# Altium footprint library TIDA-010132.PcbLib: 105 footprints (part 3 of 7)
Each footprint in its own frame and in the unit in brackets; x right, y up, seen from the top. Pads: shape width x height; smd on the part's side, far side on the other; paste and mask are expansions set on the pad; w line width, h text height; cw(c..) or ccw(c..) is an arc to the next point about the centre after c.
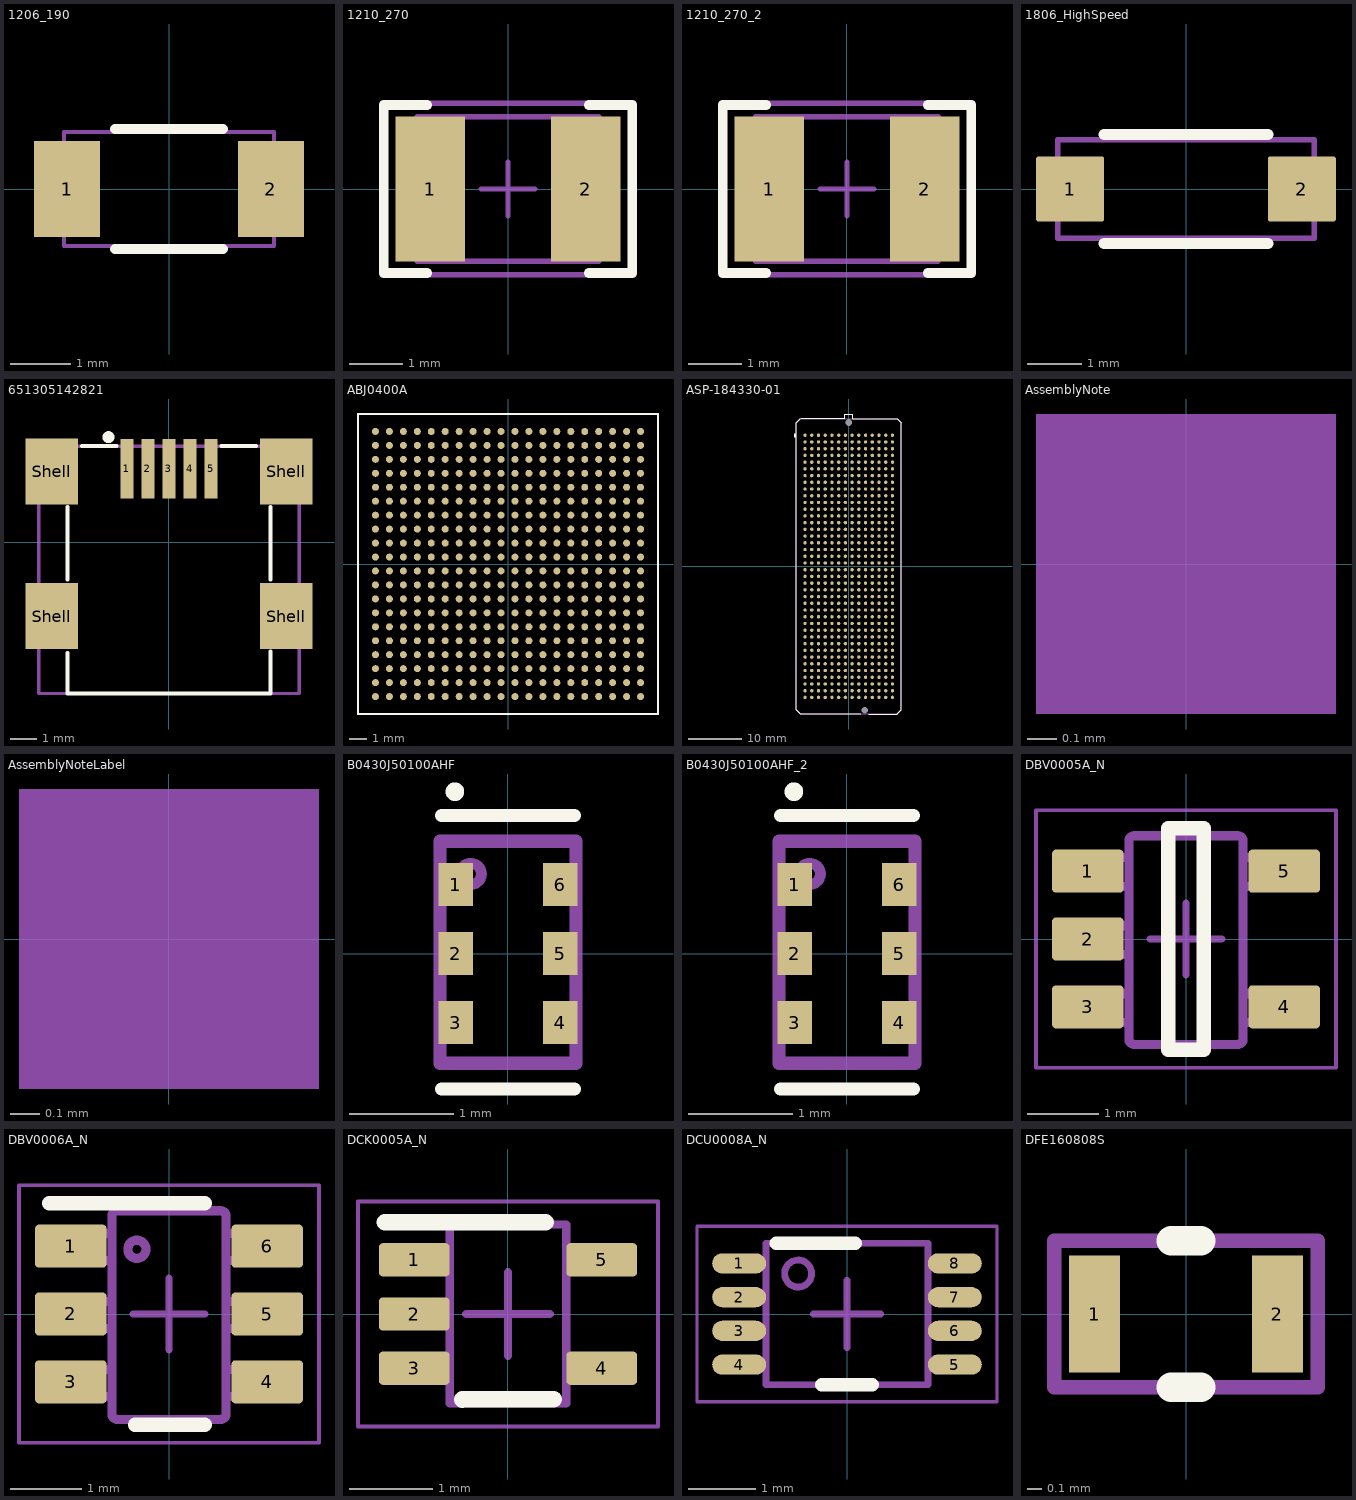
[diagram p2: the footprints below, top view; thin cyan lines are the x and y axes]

## 1206_190 [mm] "1206_190"
height 1.9
pads (2):
  rect 1.1x1.6 smd: 1(-1.7,0) 2(1.7,0)
Top Overlay:
  lines w0.17: -0.9,-1 0.9,-1 ; -0.9,1 0.9,1
Mechanical 5:
  lines w0.07: -1.75,-0.95 -1.75,0.95 1.75,0.95 1.75,-0.95 -1.75,-0.95
  text ".Designator" at -1.5,-0.4 h0.46
3D body: height 1.9, standoff 0, extent 1.301,-0.949 1.749,0.949
3D body: height 1.9, standoff 0, extent -1.299,-0.949 1.299,0.949
3D body: height 1.9, standoff 0, extent -1.749,-0.949 -1.301,0.949

## 1210_270 [mm] "1210"
height 2.7
pads (2):
  rect 1.3x2.7 smd: 1(-1.45,0) 2(1.45,0)
Top Overlay:
  lines w0.178: -1.511,-1.568 -2.316,-1.568 -2.316,1.568 -1.511,1.568 ; 1.511,-1.568 2.316,-1.568 2.316,1.568 1.511,1.568
Mechanical 5:
  lines w0.1: -1.7,-1.35 -1.7,1.35 1.7,1.35 1.7,-1.35 -1.7,-1.35
  text ".Designator" at -1.4,-0.375 h0.46
Mechanical 13:
  lines w0.1: -1.2,-1.35 -1.2,1.35 ; 1.2,-1.35 1.2,1.35 ; -1.7,-1.35 1.7,-1.35 1.7,1.35 -1.7,1.35 -1.7,-1.35
Mechanical 15:
  lines w0.1: -0.5,0 0.5,0 ; 0,-0.5 0,0.5 ; -2.35,-1.6 2.35,-1.6 2.35,1.6 -2.35,1.6 -2.35,-1.6
3D body: height 2.7, standoff 0, extent 1.201,-1.349 1.699,1.349
3D body: height 2.7, standoff 0, extent -1.199,-1.349 1.199,1.349
3D body: height 2.7, standoff 0, extent -1.699,-1.349 -1.201,1.349

## 1210_270_2 [mm]
pads (2):
  rect 1.3x2.7 smd: 1(-1.45,0) 2(1.45,0)
Top Overlay:
  lines w0.178: -1.511,-1.568 -2.316,-1.568 -2.316,1.568 -1.511,1.568 ; 1.511,-1.568 2.316,-1.568 2.316,1.568 1.511,1.568
Mechanical 5:
  lines w0.1: -1.7,-1.35 -1.7,1.35 1.7,1.35 1.7,-1.35 -1.7,-1.35
  text ".Designator" at -1.4,-0.375 h0.46
Mechanical 13:
  lines w0.1: -1.2,-1.35 -1.2,1.35 ; 1.2,-1.35 1.2,1.35 ; -1.7,-1.35 1.7,-1.35 1.7,1.35 -1.7,1.35 -1.7,-1.35
Mechanical 15:
  lines w0.1: -0.5,0 0.5,0 ; 0,-0.5 0,0.5 ; -2.35,-1.6 2.35,-1.6 2.35,1.6 -2.35,1.6 -2.35,-1.6
3D body: height 2.7, standoff 0, extent 1.201,-1.349 1.699,1.349
3D body: height 2.7, standoff 0, extent -1.199,-1.349 1.199,1.349
3D body: height 2.7, standoff 0, extent -1.699,-1.349 -1.201,1.349

## 1806_HighSpeed [mm] "Wurth recommended land pattern"
height 1.85
pads (2):
  rrect8% 1.25x1.2 smd: 1(-2.125,0) 2(2.125,0)
Top Overlay:
  lines w0.2: -1.5,-1 1.5,-1 ; -1.5,1 1.5,1
Mechanical 5:
  lines w0.1: -2.35,-0.9 -2.35,0.9 2.35,0.9 2.35,-0.9 -2.35,-0.9
  text ".Designator" at -1.7,-0.6 h0.46
3D body "1806.stp": height 1.61, standoff 0.01, extent -2.25,-0.8 2.25,0.8

## 651305142821 [mm] "5 pins"
height 4
pads (9):
  rect 0.5x2.25 smd: 1(-1.6,2.8) 2(-0.8,2.8) 3(0,2.8) 4(0.8,2.8) 5(1.6,2.8)
  rect 2x2.5 smd: Shell(-4.45,-2.8) Shell(-4.45,2.7) Shell(4.45,-2.8) Shell(4.45,2.7)
Top Overlay:
  circle w0.254: c-2.3,4 r0.1
  lines w0.152: -3.85,-4.2 -3.85,-5.74 3.85,-5.74 ; -3.85,-1.4 -3.85,1.35 ; -3.3,3.66 -1.99,3.66 ; 2,3.66 3.3,3.66 ; 3.85,-5.74 3.85,-4.15 ; 3.85,-1.4 3.85,1.35
Mechanical 5:
  lines w0.127: -4.95,-5.74 4.95,-5.74 4.95,3.66 -4.95,3.66 -4.95,-5.74
Mechanical 13:
  lines w0.127: -4.95,-5.74 -4.95,3.66 4.95,3.66 4.95,-5.74 -4.95,-5.74
3D body "651305142821.stp": height -0.4, standoff -4.5, extent -4.95,-5.74 4.95,3.66

## ABJ0400A [mm] "BGA, 400-Leads, Body 17.2x17.2mm, Pitch 0.8mm"
height 2.65
pads (400):
  round 0.4 smd: A1(-7.6,7.6) A2(-6.8,7.6) A3(-6,7.6) A4(-5.2,7.6) A5(-4.4,7.6) A6(-3.6,7.6) A7(-2.8,7.6) A8(-2,7.6) A9(-1.2,7.6) A10(-0.4,7.6) A11(0.4,7.6) A12(1.2,7.6) A13(2,7.6) A14(2.8,7.6) A15(3.6,7.6) A16(4.4,7.6) A17(5.2,7.6) A18(6,7.6) A19(6.8,7.6) A20(7.6,7.6) B1(-7.6,6.8) B2(-6.8,6.8) B3(-6,6.8) B4(-5.2,6.8) B5(-4.4,6.8) B6(-3.6,6.8) B7(-2.8,6.8) B8(-2,6.8) B9(-1.2,6.8) B10(-0.4,6.8) B11(0.4,6.8) B12(1.2,6.8) B13(2,6.8) B14(2.8,6.8) B15(3.6,6.8) B16(4.4,6.8) B17(5.2,6.8) B18(6,6.8) B19(6.8,6.8) B20(7.6,6.8) C1(-7.6,6) C2(-6.8,6) C3(-6,6) C4(-5.2,6) C5(-4.4,6) C6(-3.6,6) C7(-2.8,6) C8(-2,6) C9(-1.2,6) C10(-0.4,6) C11(0.4,6) C12(1.2,6) C13(2,6) C14(2.8,6) C15(3.6,6) C16(4.4,6) C17(5.2,6) C18(6,6) C19(6.8,6) C20(7.6,6) D1(-7.6,5.2) D2(-6.8,5.2) D3(-6,5.2) D4(-5.2,5.2) D5(-4.4,5.2) D6(-3.6,5.2) D7(-2.8,5.2) D8(-2,5.2) D9(-1.2,5.2) D10(-0.4,5.2) D11(0.4,5.2) D12(1.2,5.2) D13(2,5.2) D14(2.8,5.2) D15(3.6,5.2) D16(4.4,5.2) D17(5.2,5.2) D18(6,5.2) D19(6.8,5.2) D20(7.6,5.2) E1(-7.6,4.4) E2(-6.8,4.4) E3(-6,4.4) E4(-5.2,4.4) E5(-4.4,4.4) E6(-3.6,4.4) E7(-2.8,4.4) E8(-2,4.4) E9(-1.2,4.4) E10(-0.4,4.4) E11(0.4,4.4) E12(1.2,4.4) E13(2,4.4) E14(2.8,4.4) E15(3.6,4.4) E16(4.4,4.4) E17(5.2,4.4) E18(6,4.4) E19(6.8,4.4) E20(7.6,4.4) F1(-7.6,3.6) F2(-6.8,3.6) F3(-6,3.6) F4(-5.2,3.6) F5(-4.4,3.6) F6(-3.6,3.6) F7(-2.8,3.6) F8(-2,3.6) F9(-1.2,3.6) F10(-0.4,3.6) F11(0.4,3.6) F12(1.2,3.6) F13(2,3.6) F14(2.8,3.6) F15(3.6,3.6) F16(4.4,3.6) F17(5.2,3.6) F18(6,3.6) F19(6.8,3.6) F20(7.6,3.6) G1(-7.6,2.8) G2(-6.8,2.8) G3(-6,2.8) G4(-5.2,2.8) G5(-4.4,2.8) G6(-3.6,2.8) G7(-2.8,2.8) G8(-2,2.8) G9(-1.2,2.8) G10(-0.4,2.8) G11(0.4,2.8) G12(1.2,2.8) G13(2,2.8) G14(2.8,2.8) G15(3.6,2.8) G16(4.4,2.8) G17(5.2,2.8) G18(6,2.8) G19(6.8,2.8) G20(7.6,2.8) H1(-7.6,2) H2(-6.8,2) H3(-6,2) H4(-5.2,2) H5(-4.4,2) H6(-3.6,2) H7(-2.8,2) H8(-2,2) H9(-1.2,2) H10(-0.4,2) H11(0.4,2) H12(1.2,2) H13(2,2) H14(2.8,2) H15(3.6,2) H16(4.4,2) H17(5.2,2) H18(6,2) H19(6.8,2) H20(7.6,2) J1(-7.6,1.2) J2(-6.8,1.2) J3(-6,1.2) J4(-5.2,1.2) J5(-4.4,1.2) J6(-3.6,1.2) J7(-2.8,1.2) J8(-2,1.2) J9(-1.2,1.2) J10(-0.4,1.2) J11(0.4,1.2) J12(1.2,1.2) J13(2,1.2) J14(2.8,1.2) J15(3.6,1.2) J16(4.4,1.2) J17(5.2,1.2) J18(6,1.2) J19(6.8,1.2) J20(7.6,1.2) K1(-7.6,0.4) K2(-6.8,0.4) K3(-6,0.4) K4(-5.2,0.4) K5(-4.4,0.4) K6(-3.6,0.4) K7(-2.8,0.4) K8(-2,0.4) K9(-1.2,0.4) K10(-0.4,0.4) K11(0.4,0.4) K12(1.2,0.4) K13(2,0.4) K14(2.8,0.4) K15(3.6,0.4) K16(4.4,0.4) K17(5.2,0.4) K18(6,0.4) K19(6.8,0.4) K20(7.6,0.4) L1(-7.6,-0.4) L2(-6.8,-0.4) L3(-6,-0.4) L4(-5.2,-0.4) L5(-4.4,-0.4) L6(-3.6,-0.4) L7(-2.8,-0.4) L8(-2,-0.4) L9(-1.2,-0.4) L10(-0.4,-0.4) L11(0.4,-0.4) L12(1.2,-0.4) L13(2,-0.4) L14(2.8,-0.4) L15(3.6,-0.4) L16(4.4,-0.4) L17(5.2,-0.4) L18(6,-0.4) L19(6.8,-0.4) L20(7.6,-0.4) M1(-7.6,-1.2) M2(-6.8,-1.2) M3(-6,-1.2) M4(-5.2,-1.2) M5(-4.4,-1.2) M6(-3.6,-1.2) M7(-2.8,-1.2) M8(-2,-1.2) M9(-1.2,-1.2) M10(-0.4,-1.2) M11(0.4,-1.2) M12(1.2,-1.2) M13(2,-1.2) M14(2.8,-1.2) M15(3.6,-1.2) M16(4.4,-1.2) M17(5.2,-1.2) M18(6,-1.2) M19(6.8,-1.2) M20(7.6,-1.2) N1(-7.6,-2) N2(-6.8,-2) N3(-6,-2) N4(-5.2,-2) N5(-4.4,-2) N6(-3.6,-2) N7(-2.8,-2) N8(-2,-2) N9(-1.2,-2) N10(-0.4,-2) N11(0.4,-2) N12(1.2,-2) N13(2,-2) N14(2.8,-2) N15(3.6,-2) N16(4.4,-2) N17(5.2,-2) N18(6,-2) N19(6.8,-2) N20(7.6,-2) P1(-7.6,-2.8) P2(-6.8,-2.8) P3(-6,-2.8) P4(-5.2,-2.8) P5(-4.4,-2.8) P6(-3.6,-2.8) P7(-2.8,-2.8) P8(-2,-2.8) P9(-1.2,-2.8) P10(-0.4,-2.8) P11(0.4,-2.8) P12(1.2,-2.8) P13(2,-2.8) P14(2.8,-2.8) P15(3.6,-2.8) P16(4.4,-2.8) P17(5.2,-2.8) P18(6,-2.8) P19(6.8,-2.8) P20(7.6,-2.8) R1(-7.6,-3.6) R2(-6.8,-3.6) R3(-6,-3.6) R4(-5.2,-3.6) R5(-4.4,-3.6) R6(-3.6,-3.6) R7(-2.8,-3.6) R8(-2,-3.6) R9(-1.2,-3.6) R10(-0.4,-3.6) R11(0.4,-3.6) R12(1.2,-3.6) R13(2,-3.6) R14(2.8,-3.6) R15(3.6,-3.6) R16(4.4,-3.6) R17(5.2,-3.6) R18(6,-3.6) R19(6.8,-3.6) R20(7.6,-3.6) T1(-7.6,-4.4) T2(-6.8,-4.4) T3(-6,-4.4) T4(-5.2,-4.4) T5(-4.4,-4.4) T6(-3.6,-4.4) T7(-2.8,-4.4) T8(-2,-4.4) T9(-1.2,-4.4) T10(-0.4,-4.4) T11(0.4,-4.4) T12(1.2,-4.4) T13(2,-4.4) T14(2.8,-4.4) T15(3.6,-4.4) T16(4.4,-4.4) T17(5.2,-4.4) T18(6,-4.4) T19(6.8,-4.4) T20(7.6,-4.4) U1(-7.6,-5.2) U2(-6.8,-5.2) U3(-6,-5.2) U4(-5.2,-5.2) U5(-4.4,-5.2) U6(-3.6,-5.2) U7(-2.8,-5.2) U8(-2,-5.2) U9(-1.2,-5.2) U10(-0.4,-5.2) U11(0.4,-5.2) U12(1.2,-5.2) U13(2,-5.2) U14(2.8,-5.2) U15(3.6,-5.2) U16(4.4,-5.2) U17(5.2,-5.2) U18(6,-5.2) U19(6.8,-5.2) U20(7.6,-5.2) V1(-7.6,-6) V2(-6.8,-6) V3(-6,-6) V4(-5.2,-6) V5(-4.4,-6) V6(-3.6,-6) V7(-2.8,-6) V8(-2,-6) V9(-1.2,-6) V10(-0.4,-6) V11(0.4,-6) V12(1.2,-6) V13(2,-6) V14(2.8,-6) V15(3.6,-6) V16(4.4,-6) V17(5.2,-6) V18(6,-6) V19(6.8,-6) V20(7.6,-6) W1(-7.6,-6.8) W2(-6.8,-6.8) W3(-6,-6.8) W4(-5.2,-6.8) W5(-4.4,-6.8) W6(-3.6,-6.8) W7(-2.8,-6.8) W8(-2,-6.8) W9(-1.2,-6.8) W10(-0.4,-6.8) W11(0.4,-6.8) W12(1.2,-6.8) W13(2,-6.8) W14(2.8,-6.8) W15(3.6,-6.8) W16(4.4,-6.8) W17(5.2,-6.8) W18(6,-6.8) W19(6.8,-6.8) W20(7.6,-6.8) Y1(-7.6,-7.6) Y2(-6.8,-7.6) Y3(-6,-7.6) Y4(-5.2,-7.6) Y5(-4.4,-7.6) Y6(-3.6,-7.6) Y7(-2.8,-7.6) Y8(-2,-7.6) Y9(-1.2,-7.6) Y10(-0.4,-7.6) Y11(0.4,-7.6) Y12(1.2,-7.6) Y13(2,-7.6) Y14(2.8,-7.6) Y15(3.6,-7.6) Y16(4.4,-7.6) Y17(5.2,-7.6) Y18(6,-7.6) Y19(6.8,-7.6) Y20(7.6,-7.6)
Top Overlay:
  lines w0.1: -8.6,-8.6 8.6,-8.6 8.6,8.6 -8.6,8.6 -8.6,-8.6
Mechanical 5:
  lines w0.1: -8.6,-8.6 -8.6,8.6 8.6,8.6 8.6,-8.6 -8.6,-8.6
  text ".Designator" at -1.7,-0.5 h0.46
3D body: height 2.65, standoff 0.3, extent -8.6,-8.6 8.6,8.6

## ASP-184330-01 [mil] "Terminal Array, 1.27mm, 40x14, SMT"
height 285
pads (1122):
  round 25 smd paste-25.2: A1(-225,975) A2(-225,925) A3(-225,875) A4(-225,825) A5(-225,775) A6(-225,725) A7(-225,675) A8(-225,625) A9(-225,575) A10(-225,525) A11(-225,475) A12(-225,425) A13(-225,375) A14(-225,325) A15(-225,275) A16(-225,225) A17(-225,175) A18(-225,125) A19(-225,75) A20(-225,25) A21(-225,-25) A22(-225,-75) A23(-225,-125) A24(-225,-175) A25(-225,-225) A26(-225,-275) A27(-225,-325) A28(-225,-375) A29(-225,-425) A30(-225,-475) A31(-225,-525) A32(-225,-575) A33(-225,-625) A34(-225,-675) A35(-225,-725) A36(-225,-775) A37(-225,-825) A38(-225,-875) A39(-225,-925) A40(-225,-975) B1(-175,975) B2(-175,925) B3(-175,875) B4(-175,825) B5(-175,775) B6(-175,725) B7(-175,675) B8(-175,625) B9(-175,575) B10(-175,525) B11(-175,475) B12(-175,425) B13(-175,375) B14(-175,325) B15(-175,275) B16(-175,225) B17(-175,175) B18(-175,125) B19(-175,75) B20(-175,25) B21(-175,-25) B22(-175,-75) B23(-175,-125) B24(-175,-175) B25(-175,-225) B26(-175,-275) B27(-175,-325) B28(-175,-375) B29(-175,-425) B30(-175,-475) B31(-175,-525) B32(-175,-575) B33(-175,-625) B34(-175,-675) B35(-175,-725) B36(-175,-775) B37(-175,-825) B38(-175,-875) B39(-175,-925) B40(-175,-975) C1(-125,975) C2(-125,925) C3(-125,875) C4(-125,825) C5(-125,775) C6(-125,725) C7(-125,675) C8(-125,625) C9(-125,575) C10(-125,525) C11(-125,475) C12(-125,425) C13(-125,375) C14(-125,325) C15(-125,275) C16(-125,225) C17(-125,175) C18(-125,125) C19(-125,75) C20(-125,25) C21(-125,-25) C22(-125,-75) C23(-125,-125) C24(-125,-175) C25(-125,-225) C26(-125,-275) C27(-125,-325) C28(-125,-375) C29(-125,-425) C30(-125,-475) C31(-125,-525) C32(-125,-575) C33(-125,-625) C34(-125,-675) C35(-125,-725) C36(-125,-775) C37(-125,-825) C38(-125,-875) C39(-125,-925) C40(-125,-975) D1(-75,975) D2(-75,925) D3(-75,875) D4(-75,825) D5(-75,775) D6(-75,725) D7(-75,675) D8(-75,625) D9(-75,575) D10(-75,525) D11(-75,475) D12(-75,425) D13(-75,375) D14(-75,325) D15(-75,275) D16(-75,225) D17(-75,175) D18(-75,125) D19(-75,75) D20(-75,25) D21(-75,-25) D22(-75,-75) D23(-75,-125) D24(-75,-175) D25(-75,-225) D26(-75,-275) D27(-75,-325) D28(-75,-375) D29(-75,-425) D30(-75,-475) D31(-75,-525) D32(-75,-575) D33(-75,-625) D34(-75,-675) D35(-75,-725) D36(-75,-775) D37(-75,-825) D38(-75,-875) D39(-75,-925) D40(-75,-975) E1(-25,975) E2(-25,925) E3(-25,875) E4(-25,825) E5(-25,775) E6(-25,725) E7(-25,675) E8(-25,625) E9(-25,575) E10(-25,525) E11(-25,475) E12(-25,425) E13(-25,375) E14(-25,325) E15(-25,275) E16(-25,225) E17(-25,175) E18(-25,125) E19(-25,75) E20(-25,25) E21(-25,-25) E22(-25,-75) E23(-25,-125) E24(-25,-175) E25(-25,-225) E26(-25,-275) E27(-25,-325) E28(-25,-375) E29(-25,-425) E30(-25,-475) E31(-25,-525) E32(-25,-575) E33(-25,-625) E34(-25,-675) E35(-25,-725) E36(-25,-775) E37(-25,-825) E38(-25,-875) E39(-25,-925) E40(-25,-975) F1(25,975) F2(25,925) F3(25,875) F4(25,825) F5(25,775) F6(25,725) F7(25,675) F8(25,625) F9(25,575) F10(25,525) F11(25,475) F12(25,425) F13(25,375) F14(25,325) F15(25,275) F16(25,225) F17(25,175) F18(25,125) F19(25,75) F20(25,25) F21(25,-25) F22(25,-75) F23(25,-125) F24(25,-175) F25(25,-225) F26(25,-275) F27(25,-325) F28(25,-375) F29(25,-425) F30(25,-475) F31(25,-525) F32(25,-575) F33(25,-625) F34(25,-675) F35(25,-725) F36(25,-775) F37(25,-825) F38(25,-875) F39(25,-925) F40(25,-975) G1(75,975) G2(75,925) G3(75,875) G4(75,825) G5(75,775) G6(75,725) G7(75,675) G8(75,625) G9(75,575) G10(75,525) G11(75,475) G12(75,425) G13(75,375) G14(75,325) G15(75,275) G16(75,225) G17(75,175) G18(75,125) G19(75,75) G20(75,25) G21(75,-25) G22(75,-75) G23(75,-125) G24(75,-175) G25(75,-225) G26(75,-275) G27(75,-325) G28(75,-375) G29(75,-425) G30(75,-475) G31(75,-525) G32(75,-575) G33(75,-625) G34(75,-675) G35(75,-725) G36(75,-775) G37(75,-825) G38(75,-875) G39(75,-925) G40(75,-975) H1(125,975) H2(125,925) H3(125,875) H4(125,825) H5(125,775) H6(125,725) H7(125,675) H8(125,625) H9(125,575) H10(125,525) H11(125,475) H12(125,425) H13(125,375) H14(125,325) H15(125,275) H16(125,225) H17(125,175) H18(125,125) H19(125,75) H20(125,25) H21(125,-25) H22(125,-75) H23(125,-125) H24(125,-175) H25(125,-225) H26(125,-275) H27(125,-325) H28(125,-375) H29(125,-425) H30(125,-475) H31(125,-525) H32(125,-575) H33(125,-625) H34(125,-675) H35(125,-725) H36(125,-775) H37(125,-825) H38(125,-875) H39(125,-925) H40(125,-975) J1(175,975) J2(175,925) J3(175,875) J4(175,825) J5(175,775) J6(175,725) J7(175,675) J8(175,625) J9(175,575) J10(175,525) J11(175,475) J12(175,425) J13(175,375) J14(175,325) J15(175,275) J16(175,225) J17(175,175) J18(175,125) J19(175,75) J20(175,25) J21(175,-25) J22(175,-75) J23(175,-125) J24(175,-175) J25(175,-225) J26(175,-275) J27(175,-325) J28(175,-375) J29(175,-425) J30(175,-475) J31(175,-525) J32(175,-575) J33(175,-625) J34(175,-675) J35(175,-725) J36(175,-775) J37(175,-825) J38(175,-875) J39(175,-925) J40(175,-975) K1(225,975) K2(225,925) K3(225,875) K4(225,825) K5(225,775) K6(225,725) K7(225,675) K8(225,625) K9(225,575) K10(225,525) K11(225,475) K12(225,425) K13(225,375) K14(225,325) K15(225,275) K16(225,225) K17(225,175) K18(225,125) K19(225,75) K20(225,25) K21(225,-25) K22(225,-75) K23(225,-125) K24(225,-175) K25(225,-225) K26(225,-275) K27(225,-325) K28(225,-375) K29(225,-425) K30(225,-475) K31(225,-525) K32(225,-575) K33(225,-625) K34(225,-675) K35(225,-725) K36(225,-775) K37(225,-825) K38(225,-875) K39(225,-925) K40(225,-975) L1(275,975) L2(275,925) L3(275,875) L4(275,825) L5(275,775) L6(275,725) L7(275,675) L8(275,625) L9(275,575) L10(275,525) L11(275,475) L12(275,425) L13(275,375) L14(275,325) L15(275,275) L16(275,225) L17(275,175) L18(275,125) L19(275,75) L20(275,25) L21(275,-25) L22(275,-75) L23(275,-125) L24(275,-175) L25(275,-225) L26(275,-275) L27(275,-325) L28(275,-375) L29(275,-425) L30(275,-475) L31(275,-525) L32(275,-575) L33(275,-625) L34(275,-675) L35(275,-725) L36(275,-775) L37(275,-825) L38(275,-875) L39(275,-925) L40(275,-975) M1(325,975) M2(325,925) M3(325,875) M4(325,825) M5(325,775) M6(325,725) M7(325,675) M8(325,625) M9(325,575) M10(325,525) M11(325,475) M12(325,425) M13(325,375) M14(325,325) M15(325,275) M16(325,225) M17(325,175) M18(325,125) M19(325,75) M20(325,25) M21(325,-25) M22(325,-75) M23(325,-125) M24(325,-175) M25(325,-225) M26(325,-275) M27(325,-325) M28(325,-375) M29(325,-425) M30(325,-475) M31(325,-525) M32(325,-575) M33(325,-625) M34(325,-675) M35(325,-725) M36(325,-775) M37(325,-825) M38(325,-875) M39(325,-925) M40(325,-975) Y1(-325,975) Y2(-325,925) Y3(-325,875) Y4(-325,825) Y5(-325,775) Y6(-325,725) Y7(-325,675) Y8(-325,625) Y9(-325,575) Y10(-325,525) Y11(-325,475) Y12(-325,425) Y13(-325,375) Y14(-325,325) Y15(-325,275) Y16(-325,225) Y17(-325,175) Y18(-325,125) Y19(-325,75) Y20(-325,25) Y21(-325,-25) Y22(-325,-75) Y23(-325,-125) Y24(-325,-175) Y25(-325,-225) Y26(-325,-275) Y27(-325,-325) Y28(-325,-375) Y29(-325,-425) Y30(-325,-475) Y31(-325,-525) Y32(-325,-575) Y33(-325,-625) Y34(-325,-675) Y35(-325,-725) Y36(-325,-775) Y37(-325,-825) Y38(-325,-875) Y39(-325,-925) Y40(-325,-975) Z1(-275,975) Z2(-275,925) Z3(-275,875) Z4(-275,825) Z5(-275,775) Z6(-275,725) Z7(-275,675) Z8(-275,625) Z9(-275,575) Z10(-275,525) Z11(-275,475) Z12(-275,425) Z13(-275,375) Z14(-275,325) Z15(-275,275) Z16(-275,225) Z17(-275,175) Z18(-275,125) Z19(-275,75) Z20(-275,25) Z21(-275,-25) Z22(-275,-75) Z23(-275,-125) Z24(-275,-175) Z25(-275,-225) Z26(-275,-275) Z27(-275,-325) Z28(-275,-375) Z29(-275,-425) Z30(-275,-475) Z31(-275,-525) Z32(-275,-575) Z33(-275,-625) Z34(-275,-675) Z35(-275,-725) Z36(-275,-775) Z37(-275,-825) Z38(-275,-875) Z39(-275,-925) Z40(-275,-975)
  round 35 on Top Paste: ""(-325,-975) ""(-325,-925) ""(-325,-875) ""(-325,-825) ""(-325,-775) ""(-325,-725) ""(-325,-675) ""(-325,-625) ""(-325,-575) ""(-325,-525) ""(-325,-475) ""(-325,-425) ""(-325,-375) ""(-325,-325) ""(-325,-275) ""(-325,-225) ""(-325,-175) ""(-325,-125) ""(-325,-75) ""(-325,-25) ""(-325,25) ""(-325,75) ""(-325,125) ""(-325,175) ""(-325,225) ""(-325,275) ""(-325,325) ""(-325,375) ""(-325,425) ""(-325,475) ""(-325,525) ""(-325,575) ""(-325,625) ""(-325,675) ""(-325,725) ""(-325,775) ""(-325,825) ""(-325,875) ""(-325,925) ""(-325,975) ""(-275,-975) ""(-275,-925) ""(-275,-875) ""(-275,-825) ""(-275,-775) ""(-275,-725) ""(-275,-675) ""(-275,-625) ""(-275,-575) ""(-275,-525) ""(-275,-475) ""(-275,-425) ""(-275,-375) ""(-275,-325) ""(-275,-275) ""(-275,-225) ""(-275,-175) ""(-275,-125) ""(-275,-75) ""(-275,-25) ""(-275,25) ""(-275,75) ""(-275,125) ""(-275,175) ""(-275,225) ""(-275,275) ""(-275,325) ""(-275,375) ""(-275,425) ""(-275,475) ""(-275,525) ""(-275,575) ""(-275,625) ""(-275,675) ""(-275,725) ""(-275,775) ""(-275,825) ""(-275,875) ""(-275,925) ""(-275,975) ""(-225,-975) ""(-225,-925) ""(-225,-875) ""(-225,-825) ""(-225,-775) ""(-225,-725) ""(-225,-675) ""(-225,-625) ""(-225,-575) ""(-225,-525) ""(-225,-475) ""(-225,-425) ""(-225,-375) ""(-225,-325) ""(-225,-275) ""(-225,-225) ""(-225,-175) ""(-225,-125) ""(-225,-75) ""(-225,-25) ""(-225,25) ""(-225,75) ""(-225,125) ""(-225,175) ""(-225,225) ""(-225,275) ""(-225,325) ""(-225,375) ""(-225,425) ""(-225,475) ""(-225,525) ""(-225,575) ""(-225,625) ""(-225,675) ""(-225,725) ""(-225,775) ""(-225,825) ""(-225,875) ""(-225,925) ""(-225,975) ""(-175,-975) ""(-175,-925) ""(-175,-875) ""(-175,-825) ""(-175,-775) ""(-175,-725) ""(-175,-675) ""(-175,-625) ""(-175,-575) ""(-175,-525) ""(-175,-475) ""(-175,-425) ""(-175,-375) ""(-175,-325) ""(-175,-275) ""(-175,-225) ""(-175,-175) ""(-175,-125) ""(-175,-75) ""(-175,-25) ""(-175,25) ""(-175,75) ""(-175,125) ""(-175,175) ""(-175,225) ""(-175,275) ""(-175,325) ""(-175,375) ""(-175,425) ""(-175,475) ""(-175,525) ""(-175,575) ""(-175,625) ""(-175,675) ""(-175,725) ""(-175,775) ""(-175,825) ""(-175,875) ""(-175,925) ""(-175,975) ""(-125,-975) ""(-125,-925) ""(-125,-875) ""(-125,-825) ""(-125,-775) ""(-125,-725) ""(-125,-675) ""(-125,-625) ""(-125,-575) ""(-125,-525) ""(-125,-475) ""(-125,-425) ""(-125,-375) ""(-125,-325) ""(-125,-275) ""(-125,-225) ""(-125,-175) ""(-125,-125) ""(-125,-75) ""(-125,-25) ""(-125,25) ""(-125,75) ""(-125,125) ""(-125,175) ""(-125,225) ""(-125,275) ""(-125,325) ""(-125,375) ""(-125,425) ""(-125,475) ""(-125,525) ""(-125,575) ""(-125,625) ""(-125,675) ""(-125,725) ""(-125,775) ""(-125,825) ""(-125,875) ""(-125,925) ""(-125,975) ""(-75,-975) ""(-75,-925) ""(-75,-875) ""(-75,-825) ""(-75,-775) ""(-75,-725) ""(-75,-675) ""(-75,-625) ""(-75,-575) ""(-75,-525) ""(-75,-475) ""(-75,-425) ""(-75,-375) ""(-75,-325) ""(-75,-275) ""(-75,-225) ""(-75,-175) ""(-75,-125) ""(-75,-75) ""(-75,-25) ""(-75,25) ""(-75,75) ""(-75,125) ""(-75,175) ""(-75,225) ""(-75,275) ""(-75,325) ""(-75,375) ""(-75,425) ""(-75,475) ""(-75,525) ""(-75,575) ""(-75,625) ""(-75,675) ""(-75,725) ""(-75,775) ""(-75,825) ""(-75,875) ""(-75,925) ""(-75,975) ""(-25,-975) ""(-25,-925) ""(-25,-875) ""(-25,-825) ""(-25,-775) ""(-25,-725) ""(-25,-675) ""(-25,-625) ""(-25,-575) ""(-25,-525) ""(-25,-475) ""(-25,-425) ""(-25,-375) ""(-25,-325) ""(-25,-275) ""(-25,-225) ""(-25,-175) ""(-25,-125) ""(-25,-75) ""(-25,-25) ""(-25,25) ""(-25,75) ""(-25,125) ""(-25,175) ""(-25,225) ""(-25,275) ""(-25,325) ""(-25,375) ""(-25,425) ""(-25,475) ""(-25,525) ""(-25,575) ""(-25,625) ""(-25,675) ""(-25,725) ""(-25,775) ""(-25,825) ""(-25,875) ""(-25,925) ""(-25,975) ""(25,-975) ""(25,-925) ""(25,-875) ""(25,-825) ""(25,-775) ""(25,-725) ""(25,-675) ""(25,-625) ""(25,-575) ""(25,-525) ""(25,-475) ""(25,-425) ""(25,-375) ""(25,-325) ""(25,-275) ""(25,-225) ""(25,-175) ""(25,-125) ""(25,-75) ""(25,-25) ""(25,25) ""(25,75) ""(25,125) ""(25,175) ""(25,225) ""(25,275) ""(25,325) ""(25,375) ""(25,425) ""(25,475) ""(25,525) ""(25,575) ""(25,625) ""(25,675) ""(25,725) ""(25,775) ""(25,825) ""(25,875) ""(25,925) ""(25,975) ""(75,-975) ""(75,-925) ""(75,-875) ""(75,-825) ""(75,-775) ""(75,-725) ""(75,-675) ""(75,-625) ""(75,-575) ""(75,-525) ""(75,-475) ""(75,-425) ""(75,-375) ""(75,-325) ""(75,-275) ""(75,-225) ""(75,-175) ""(75,-125) ""(75,-75) ""(75,-25) ""(75,25) ""(75,75) ""(75,125) ""(75,175) ""(75,225) ""(75,275) ""(75,325) ""(75,375) ""(75,425) ""(75,475) ""(75,525) ""(75,575) ""(75,625) ""(75,675) ""(75,725) ""(75,775) ""(75,825) ""(75,875) ""(75,925) ""(75,975) ""(125,-975) ""(125,-925) ""(125,-875) ""(125,-825) ""(125,-775) ""(125,-725) ""(125,-675) ""(125,-625) ""(125,-575) ""(125,-525) ""(125,-475) ""(125,-425) ""(125,-375) ""(125,-325) ""(125,-275) ""(125,-225) ""(125,-175) ""(125,-125) ""(125,-75) ""(125,-25) ""(125,25) ""(125,75) ""(125,125) ""(125,175) ""(125,225) ""(125,275) ""(125,325) ""(125,375) ""(125,425) ""(125,475) ""(125,525) ""(125,575) ""(125,625) ""(125,675) ""(125,725) ""(125,775) ""(125,825) ""(125,875) ""(125,925) ""(125,975) ""(175,-975) ""(175,-925) ""(175,-875) ""(175,-825) ""(175,-775) ""(175,-725) ""(175,-675) ""(175,-625) ""(175,-575) ""(175,-525) ""(175,-475) ""(175,-425) ""(175,-375) ""(175,-325) ""(175,-275) ""(175,-225) ""(175,-175) ""(175,-125) ""(175,-75) ""(175,-25) ""(175,25) ""(175,75) ""(175,125) ""(175,175) ""(175,225) ""(175,275) ""(175,325) ""(175,375) ""(175,425) ""(175,475) ""(175,525) ""(175,575) ""(175,625) ""(175,675) ""(175,725) ""(175,775) ""(175,825) ""(175,875) ""(175,925) ""(175,975) ""(225,-975) ""(225,-925) ""(225,-875) ""(225,-825) ""(225,-775) ""(225,-725) ""(225,-675) ""(225,-625) ""(225,-575) ""(225,-525) ""(225,-475) ""(225,-425) ""(225,-375) ""(225,-325) ""(225,-275) ""(225,-225) ""(225,-175) ""(225,-125) ""(225,-75) ""(225,-25) ""(225,25) ""(225,75) ""(225,125) ""(225,175) ""(225,225) ""(225,275) ""(225,325) ""(225,375) ""(225,425) ""(225,475) ""(225,525) ""(225,575) ""(225,625) ""(225,675) ""(225,725) ""(225,775) ""(225,825) ""(225,875) ""(225,925) ""(225,975) ""(275,-975) ""(275,-925) ""(275,-875) ""(275,-825) ""(275,-775) ""(275,-725) ""(275,-675) ""(275,-625) ""(275,-575) ""(275,-525) ""(275,-475) ""(275,-425) ""(275,-375) ""(275,-325) ""(275,-275) ""(275,-225) ""(275,-175) ""(275,-125) ""(275,-75) ""(275,-25) ""(275,25) ""(275,75) ""(275,125) ""(275,175) ""(275,225) ""(275,275) ""(275,325) ""(275,375) ""(275,425) ""(275,475) ""(275,525) ""(275,575) ""(275,625) ""(275,675) ""(275,725) ""(275,775) ""(275,825) ""(275,875) ""(275,925) ""(275,975) ""(325,-975) ""(325,-925) ""(325,-875) ""(325,-825) ""(325,-775) ""(325,-725) ""(325,-675) ""(325,-625) ""(325,-575) ""(325,-525) ""(325,-475) ""(325,-425) ""(325,-375) ""(325,-325) ""(325,-275) ""(325,-225) ""(325,-175) ""(325,-125) ""(325,-75) ""(325,-25) ""(325,25) ""(325,75) ""(325,125) ""(325,175) ""(325,225) ""(325,275) ""(325,325) ""(325,375) ""(325,425) ""(325,475) ""(325,525) ""(325,575) ""(325,625) ""(325,675) ""(325,725) ""(325,775) ""(325,825) ""(325,875) ""(325,925) ""(325,975)
  round 0 hole 50 unplated: ""(0,1070.5) ""(120,-1070.5)
Top Overlay:
  region: -405.51,988.19 -405.51,956.69 -392.99,956.69 -392.99,988.19
  lines w7.87: -359,1098 -389,1068 -389,-1068 -359,-1098 89.92,-1098 ; -356.5,1100.5 -30,1100.5 -30,1133 30,1133 30,1098 359,1098 389,1068 389,-1068 359,-1098 ; 149.69,-1098.43 359,-1098.43
Mechanical 5:
  lines w3.94: -30,1098 -30,1133 30,1133 30,1098 ; -389,-1068 -389,1068 -359,1098 -342.5,1098 -79,1098 -27.5,1098 27.5,1098 79,1098 342.5,1098 359,1098 389,1068 389,-1068 359,-1098 342.5,-1098 180,-1098 120,-1098 -120,-1098 -180,-1098 -342.5,-1098 -359,-1098 -389,-1068
  text ".Designator" at -82.68,-7.87 h18
3D body "ASP-184330-01.stp": height 289, standoff -41, extent -389,-1098 389,1133

## AssemblyNote [mil] "Assembly Note"
Mechanical 5:
  rectangle: -20,-20 20,20
  text ".Comment" at 45,-20 h18
  text ".Designator" at -165,-20 h18

## AssemblyNoteLabel [mil] "Assembly Note for PCB Labels"
Mechanical 5:
  rectangle: -19.96,-20 20.04,20
  text ".Designator" at -165,-20 h18
  text "Install label in silkscreened box after final wash.  Text shall be 8 pt font.  Text shall be per the Label Table in the PDF schematic." at 45,-20 h18

## B0430J50100AHF [mm] "Anaren Ultra Low Profile 0805 Balun 50  to 100  Balanced"
height 0.75
pads (6):
  rect 0.33x0.41 smd mask+0.075: 1(-0.498,0.66) 2(-0.498,0) 3(-0.498,-0.66) 4(0.498,-0.66) 5(0.498,0) 6(0.498,0.66)
Top Overlay:
  circle w0.127: c-0.508,1.549 r0.025
  lines w0.127: -0.635,-1.295 0.635,-1.295 ; -0.635,1.321 0.635,1.321
Mechanical 5:
  circle w0.102: c-0.356,0.762 r0.102
  lines w0.127: -0.65,-1.05 -0.65,1.075 0.65,1.075 0.65,-1.05 -0.65,-1.05
  text ".Designator" at -0.127,1.143 h0.46
3D body: height 0.75, standoff 0, extent -0.714,-1.114 0.714,1.139
3D body: height 0.76, standoff 0.75, extent -0.457,0.661 -0.255,0.863

## B0430J50100AHF_2 [mm]
pads (6):
  rect 0.33x0.41 smd mask+0.075: 1(-0.498,0.66) 2(-0.498,0) 3(-0.498,-0.66) 4(0.498,-0.66) 5(0.498,0) 6(0.498,0.66)
Top Overlay:
  circle w0.127: c-0.508,1.549 r0.025
  lines w0.127: -0.635,-1.295 0.635,-1.295 ; -0.635,1.321 0.635,1.321
Mechanical 5:
  circle w0.102: c-0.356,0.762 r0.102
  lines w0.127: -0.65,-1.05 -0.65,1.075 0.65,1.075 0.65,-1.05 -0.65,-1.05
  text ".Designator" at -0.127,1.143 h0.46
3D body: height 0.75, standoff 0, extent -0.714,-1.114 0.714,1.138
3D body: height 0.76, standoff 0.75, extent -0.457,0.661 -0.255,0.863

## DBV0005A_N [mm] "SOT23, 5-Leads, Body 2.9x1.6mm, Pitch 0.95mm, Lead Span 2.8mm, IPC Medium Density"
height 1.45
pads (5):
  rrect17% 1x0.6 smd: 1(-1.375,0.95) 2(-1.375,0) 3(-1.375,-0.95) 4(1.375,-0.95) 5(1.375,0.95)
Top Overlay:
  lines w0.2: -0.25,-1.55 -0.25,1.55 0.25,1.55 0.25,-1.55 -0.25,-1.55
Mechanical 5:
  lines w0.127: -0.801,1.371 cw(c-0.725,1.37) -0.725,1.446 ; -0.801,1.37 -0.801,1.371 ; -0.801,1.37 -0.801,-1.399 -0.801,-1.4 ccw(c-0.725,-1.399) -0.725,-1.475 ; -0.725,-1.475 0.723,-1.475 0.724,-1.475 ccw(c0.723,-1.399) 0.799,-1.4 0.799,-1.399 0.799,1.37 ; -0.725,-1.475 -0.725,-1.475 ; -0.725,1.446 -0.725,1.446 ; -0.725,1.446 0.723,1.446 0.724,1.446 cw(c0.723,1.37) 0.799,1.371 ; 0.799,1.37 0.799,1.371 ; -1.423,-1.167 -1.423,-0.767 -1.199,-0.767 -1.105,-0.767 -1.088,-0.767 -0.835,-0.767 -0.801,-0.767 -0.801,-1.167 -0.835,-1.167 -1.088,-1.167 -1.105,-1.167 -1.199,-1.167 -1.423,-1.167 ; -1.423,-0.215 -1.423,0.186 -1.199,0.186 -1.105,0.186 -1.088,0.186 -0.835,0.186 -0.801,0.186 -0.801,-0.215 -0.835,-0.215 -1.088,-0.215 -1.105,-0.215 -1.199,-0.215 -1.423,-0.215 ; -1.423,0.738 -1.423,1.138 -1.199,1.138 -1.105,1.138 -1.088,1.138 -0.835,1.138 -0.801,1.138 -0.801,0.738 -0.835,0.738 -1.088,0.738 -1.105,0.738 -1.199,0.738 -1.423,0.738 ; 0.799,-1.167 0.834,-1.167 1.087,-1.167 1.103,-1.167 1.198,-1.167 1.422,-1.167 1.422,-0.767 1.198,-0.767 1.103,-0.767 1.087,-0.767 0.834,-0.767 0.799,-0.767 0.799,-1.167 ; 0.799,0.738 0.834,0.738 1.087,0.738 1.103,0.738 1.198,0.738 1.422,0.738 1.422,1.138 1.198,1.138 1.103,1.138 1.087,1.138 0.834,1.138 0.799,1.138 0.799,0.738
  text ".Designator" at -0.25,0.95 h0.46
Mechanical 15:
  lines w0.05: -2.1,-1.8 -2.1,1.8 2.1,1.8 2.1,-1.8 -2.1,-1.8
  lines w0.1: -0.5,0 0.5,0 ; 0,-0.5 0,0.5
3D body "DBV0005A.stp": height 1.09, standoff 0, extent -1.422,-1.461 1.423,1.46

## DBV0006A_N [mm] "SOT23, 6-Leads, Body 2.9x1.6mm, Pitch 0.95mm, Lead Span 2.8mm, IPC Medium Density"
height 1.45
pads (6):
  rrect17% 1x0.6 smd: 1(-1.375,0.95) 2(-1.375,0) 3(-1.375,-0.95) 4(1.375,-0.95) 5(1.375,0) 6(1.375,0.95)
Top Overlay:
  lines w0.2: -1.675,1.55 0.5,1.55 ; -0.475,-1.55 0.5,-1.55
Mechanical 5:
  lines w0.127: 0.724,-1.475 ccw(c0.723,-1.399) 0.8,-1.399 0.8,1.37 ccw(c0.723,1.37) 0.724,1.446 ; 0.723,-1.475 0.724,-1.475 ; 0.723,-1.475 -0.724,-1.475 -0.725,-1.475 cw(c-0.724,-1.399) -0.801,-1.399 -0.801,1.37 cw(c-0.724,1.37) -0.725,1.446 -0.724,1.446 0.723,1.446 ; 0.723,1.446 0.724,1.446 ; -1.423,-1.154 -1.206,-1.154 -1.113,-1.154 -1.081,-1.154 -0.828,-1.154 -0.801,-1.154 -0.801,-0.78 -0.828,-0.78 -1.081,-0.78 -1.113,-0.78 -1.206,-0.78 -1.423,-0.78 -1.423,-1.154 ; -1.423,-0.202 -1.206,-0.202 -1.113,-0.202 -1.081,-0.202 -0.828,-0.202 -0.801,-0.202 -0.801,0.173 -0.828,0.173 -1.081,0.173 -1.113,0.173 -1.206,0.173 -1.423,0.173 -1.423,-0.202 ; -1.423,0.751 -1.206,0.751 -1.113,0.751 -1.081,0.751 -0.828,0.751 -0.801,0.751 -0.801,1.125 -0.828,1.125 -1.081,1.125 -1.113,1.125 -1.206,1.125 -1.423,1.125 -1.423,0.751 ; -0.577,0.906 cw(c-0.45,0.906) -0.323,0.906 cw(c-0.45,0.906) -0.577,0.906 ; 0.8,-1.154 0.827,-1.154 1.08,-1.154 1.112,-1.154 1.205,-1.154 1.422,-1.154 1.422,-0.78 1.205,-0.78 1.112,-0.78 1.08,-0.78 0.827,-0.78 0.8,-0.78 0.8,-1.154 ; 0.8,-0.202 0.827,-0.202 1.08,-0.202 1.112,-0.202 1.205,-0.202 1.422,-0.202 1.422,0.173 1.205,0.173 1.112,0.173 1.08,0.173 0.827,0.173 0.8,0.173 0.8,-0.202 ; 0.8,0.751 0.827,0.751 1.08,0.751 1.112,0.751 1.205,0.751 1.422,0.751 1.422,1.125 1.205,1.125 1.112,1.125 1.08,1.125 0.827,1.125 0.8,1.125 0.8,0.751
  text ".Designator" at -0.075,0.925 h0.46
Mechanical 15:
  lines w0.05: -2.1,-1.8 2.1,-1.8 2.1,1.8 -2.1,1.8 -2.1,-1.8
  lines w0.1: -0.5,0 0.5,0 ; 0,-0.5 0,0.5
3D body "DBV0006A.stp": height 1.12, standoff 0, extent -1.422,-1.461 1.423,1.46

## DCK0005A_N [mm] "SOT353, 5-Leads, Body 2x1.3mm, Pitch 0.65mm, Lead Span 2.1mm, IPC Medium Density"
height 1.1
pads (5):
  rrect25% 0.85x0.4 smd: 1(-1.125,0.65) 2(-1.125,0) 3(-1.125,-0.65) 4(1.125,-0.65) 5(1.125,0.65)
Top Overlay:
  lines w0.2: -1.475,1.1 0.45,1.1 ; -0.55,-1.025 0.55,-1.025
Mechanical 5:
  lines w0.1: -0.7,-1.075 -0.7,1.075 0.7,1.075 0.7,-1.075 -0.7,-1.075
  lines w0.127: -0.865,0.762 -0.853,0.762 ; -0.711,-0.763 -0.853,-0.763 -0.865,-0.763 -0.959,-0.763 -1.143,-0.763 -1.143,-0.538 -0.959,-0.538 -0.865,-0.538 -0.853,-0.538 -0.711,-0.538 ; -0.711,-0.113 -0.853,-0.113 -0.865,-0.113 -0.959,-0.113 -1.143,-0.113 -1.143,0.112 -0.959,0.112 -0.865,0.112 -0.853,0.112 -0.711,0.112 ; -0.711,0.537 -0.853,0.537 -0.865,0.537 -0.959,0.537 -1.143,0.537 -1.143,0.762 -0.959,0.762 -0.711,0.762 ; 0.711,-0.763 0.847,-0.763 0.859,-0.763 0.953,-0.763 1.137,-0.763 1.137,-0.538 0.953,-0.538 0.859,-0.538 0.847,-0.538 0.711,-0.538 ; 0.711,0.537 0.847,0.537 0.859,0.537 0.953,0.537 1.137,0.537 1.137,0.762 0.953,0.762 0.859,0.762 0.847,0.762 0.711,0.762
  text ".Designator" at 0.152,-0.518 h0.46
Mechanical 15:
  lines w0.05: -1.8,-1.35 -1.8,1.35 1.8,1.35 1.8,-1.35 -1.8,-1.35
  lines w0.1: -0.5,0 0.5,0 ; 0,-0.5 0,0.5
3D body "DCK0005A.stp": height 0.95, standoff 0, extent -1.14,-1 1.14,1

## DCU0008A_N [mm] "TSSOP, 8-Leads, Body 2x2.3mm, Pitch 0.5mm, IPC Medium Density"
height 0.9
pads (8):
  oval 0.8x0.3 smd: 1(-1.6,0.75) 2(-1.6,0.25) 3(-1.6,-0.25) 4(-1.6,-0.75) 5(1.6,-0.75) 6(1.6,-0.25) 7(1.6,0.25) 8(1.6,0.75)
Top Overlay:
  lines w0.2: -1.05,1.05 0.125,1.05 ; -0.375,-1.05 0.375,-1.05
Mechanical 5:
  circle w0.1: c-0.725,0.6 r0.2
  lines w0.1: -1.2,-1.05 1.2,-1.05 1.2,1.05 -1.2,1.05 -1.2,-1.05
  text ".Designator" at -1.016,-0.489 h0.46
Mechanical 15:
  lines w0.05: -2.225,-1.3 -2.225,1.3 2.225,1.3 2.225,-1.3 -2.225,-1.3
  lines w0.1: -0.5,0 0.5,0 ; 0,-0.5 0,0.5
3D body "DCU0008A.stp": height 0.9, standoff 0, extent -1.561,-1 1.561,1

## DFE160808S [mm] "SMD, 2-Leads, Body 1.6x0.8mm"
height 0.8
pads (2):
  rect 0.35x0.8 smd: 1(-0.625,0) 2(0.625,0)
Top Overlay:
  lines w0.2: -0.1,-0.5 0.1,-0.5 ; -0.1,0.5 0.1,0.5
Mechanical 5:
  lines w0.1: -0.9,-0.5 -0.9,0.5 0.9,0.5 0.9,-0.5 -0.9,-0.5
  text ".Designator" at -0.7,-0.2 h0.46
3D body: height 0.8, standoff 0, extent -0.6,-0.5 0.6,0.5
3D body: height 0.8, standoff 0, extent -0.9,-0.5 -0.6,0.5
3D body: height 0.8, standoff 0, extent 0.6,-0.5 0.9,0.5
